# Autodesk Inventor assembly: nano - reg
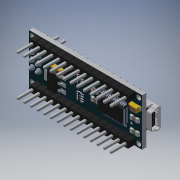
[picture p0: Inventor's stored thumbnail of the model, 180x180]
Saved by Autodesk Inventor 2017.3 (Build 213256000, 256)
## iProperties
Part Number: nano - reg
Material: Générique
Document SubType Name: Modeling
Designer: ficho
Density: 1 g/cm^3
Appearance: Par défaut
Author: ficho
Revision Number: ANY
Part Number: cap106C
Part Number: reset button
Document SubType Name: Assembly
Part Number: nano-board
Part Number: MINI USB CONTACT
Part Number: MINIUSBCORE
Part Number: MINIUSB - MEASURED
Part Number: 16mhz crystal - measured
Part Number: 102 RESISTOR PACK
Part Number: smt_resistor222
Part Number: ftdi FT232rl
Part Number: MINIUSBSHELL
Part Number: 2pin_header__02
Part Number: reset core
Part Number: NANO DIODE
Part Number: reset shell
Part Number: 189 RESISTOR PACK
Part Number: led
Part Number: 15pin_header__
Created: 2017-08
Part Number: arduino nano
Description: STEP AP214
Title: arduino nano.STEP
Author: Arthur
Sending System: SolidWorks 2015
Preprocessor: SwSTEP 2.0
Part Number: atmega328
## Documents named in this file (22)
- **C:\Users\ficho\Desktop\réforme\activité rentrée\arduino nano.iam*LocalDocs*xUbm2zgl2Fnrdusgv0bqnrldiUh*nano - reg.ipt
- **C:\Users\ficho\Desktop\réforme\activité rentrée\arduino nano.iam*LocalDocs*xHwoyo3blWehxurkrW2blyuknGa*cap106C.ipt
- **C:\Users\ficho\Desktop\réforme\activité rentrée\arduino nano.iam*LocalDocs*xBuus3cyrIowfu5giSw020mvfYf*reset button.iam
- **C:\Users\ficho\Desktop\réforme\activité rentrée\arduino nano.iam*LocalDocs*xTnmtstsbUx5ye5ocYofjtmrr0e*reset core.ipt
- **C:\Users\ficho\Desktop\réforme\activité rentrée\arduino nano.iam*LocalDocs*xUk4nsjem1sbde1ohW0bmwhsiZd*reset shell.ipt
- **C:\Users\ficho\Desktop\réforme\activité rentrée\arduino nano.iam*LocalDocs*x1nsqz3fq1fkuumsyBzehov4fRd*nano-board.ipt
- **C:\Users\ficho\Desktop\réforme\activité rentrée\arduino nano.iam*LocalDocs*x04oiaxhaVtcteksh24hk4wwwIb*MINI USB CONTACT.ipt
- **C:\Users\ficho\Desktop\réforme\activité rentrée\arduino nano.iam*LocalDocs*xAzfyq05iXrrief4kJkwgn4gbSg*MINIUSBCORE.ipt
- **C:\Users\ficho\Desktop\réforme\activité rentrée\arduino nano.iam*LocalDocs*xDhrty1enNp2eu0cyBn221sycMf*MINIUSB - MEASURED.iam
- **C:\Users\ficho\Desktop\réforme\activité rentrée\arduino nano.iam*LocalDocs*xOtrkrkl2Ksz3ew0v5onndirsVg*MINIUSBSHELL.ipt
- **C:\Users\ficho\Desktop\réforme\activité rentrée\arduino nano.iam*LocalDocs*xFlslegvtT5pwe4s5S2ipkv1oGd*16mhz crystal - measured.ipt
- **C:\Users\ficho\Desktop\réforme\activité rentrée\arduino nano.iam*LocalDocs*xRtiaxvgoL3yeu4coV4jdqpf4Tb*102 RESISTOR PACK.ipt
- **C:\Users\ficho\Desktop\réforme\activité rentrée\arduino nano.iam*LocalDocs*xNmezckr2IezmucglFouohjep1g*smt_resistor222.ipt
- **C:\Users\ficho\Desktop\réforme\activité rentrée\arduino nano.iam*LocalDocs*xM2xbrphbCnywums3Sn0khqi2Ze*ftdi FT232rl.ipt
- **C:\Users\ficho\Desktop\réforme\activité rentrée\arduino nano.iam*LocalDocs*xNvz1eurjQwioejspPu50vuihUb*2pin_header__02.ipt
- **C:\Users\ficho\Desktop\réforme\activité rentrée\arduino nano.iam*LocalDocs*xUxjrq5maOlvqevgiOlq13oel5d*NANO DIODE.ipt
- **C:\Users\ficho\Desktop\réforme\activité rentrée\arduino nano.iam*LocalDocs*xZgaarrffOj3ae20qZlun5vssUh*189 RESISTOR PACK.ipt
- **C:\Users\ficho\Desktop\réforme\activité rentrée\arduino nano.iam*LocalDocs*xV5pm2vz35kclum4xAsy55weaQd*led.ipt
- **C:\Users\ficho\Desktop\réforme\activité rentrée\arduino nano.iam*LocalDocs*xV0mxbc0uH33jeesxUl5xqucqXe*15pin_header__.ipt
- **C:\Users\ficho\Desktop\réforme\activité rentrée\arduino nano.iam*LocalDocs*xXtzb4dje5isiur0oVjr0inf3Qc*arduino nano.iam
- **C:\Users\ficho\Desktop\réforme\activité rentrée\arduino nano.iam*LocalDocs*xZjol2fkhAfraemoySzwrxkxkKe*atmega328.ipt
- C:\Users\ficho\Desktop\réforme\activité rentrée\arduino nano.iam
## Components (1 placed, 1 different names)
1. arduino nano:1 [sub-assembly]
